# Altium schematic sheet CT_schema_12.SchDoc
size 389 x 385 mm
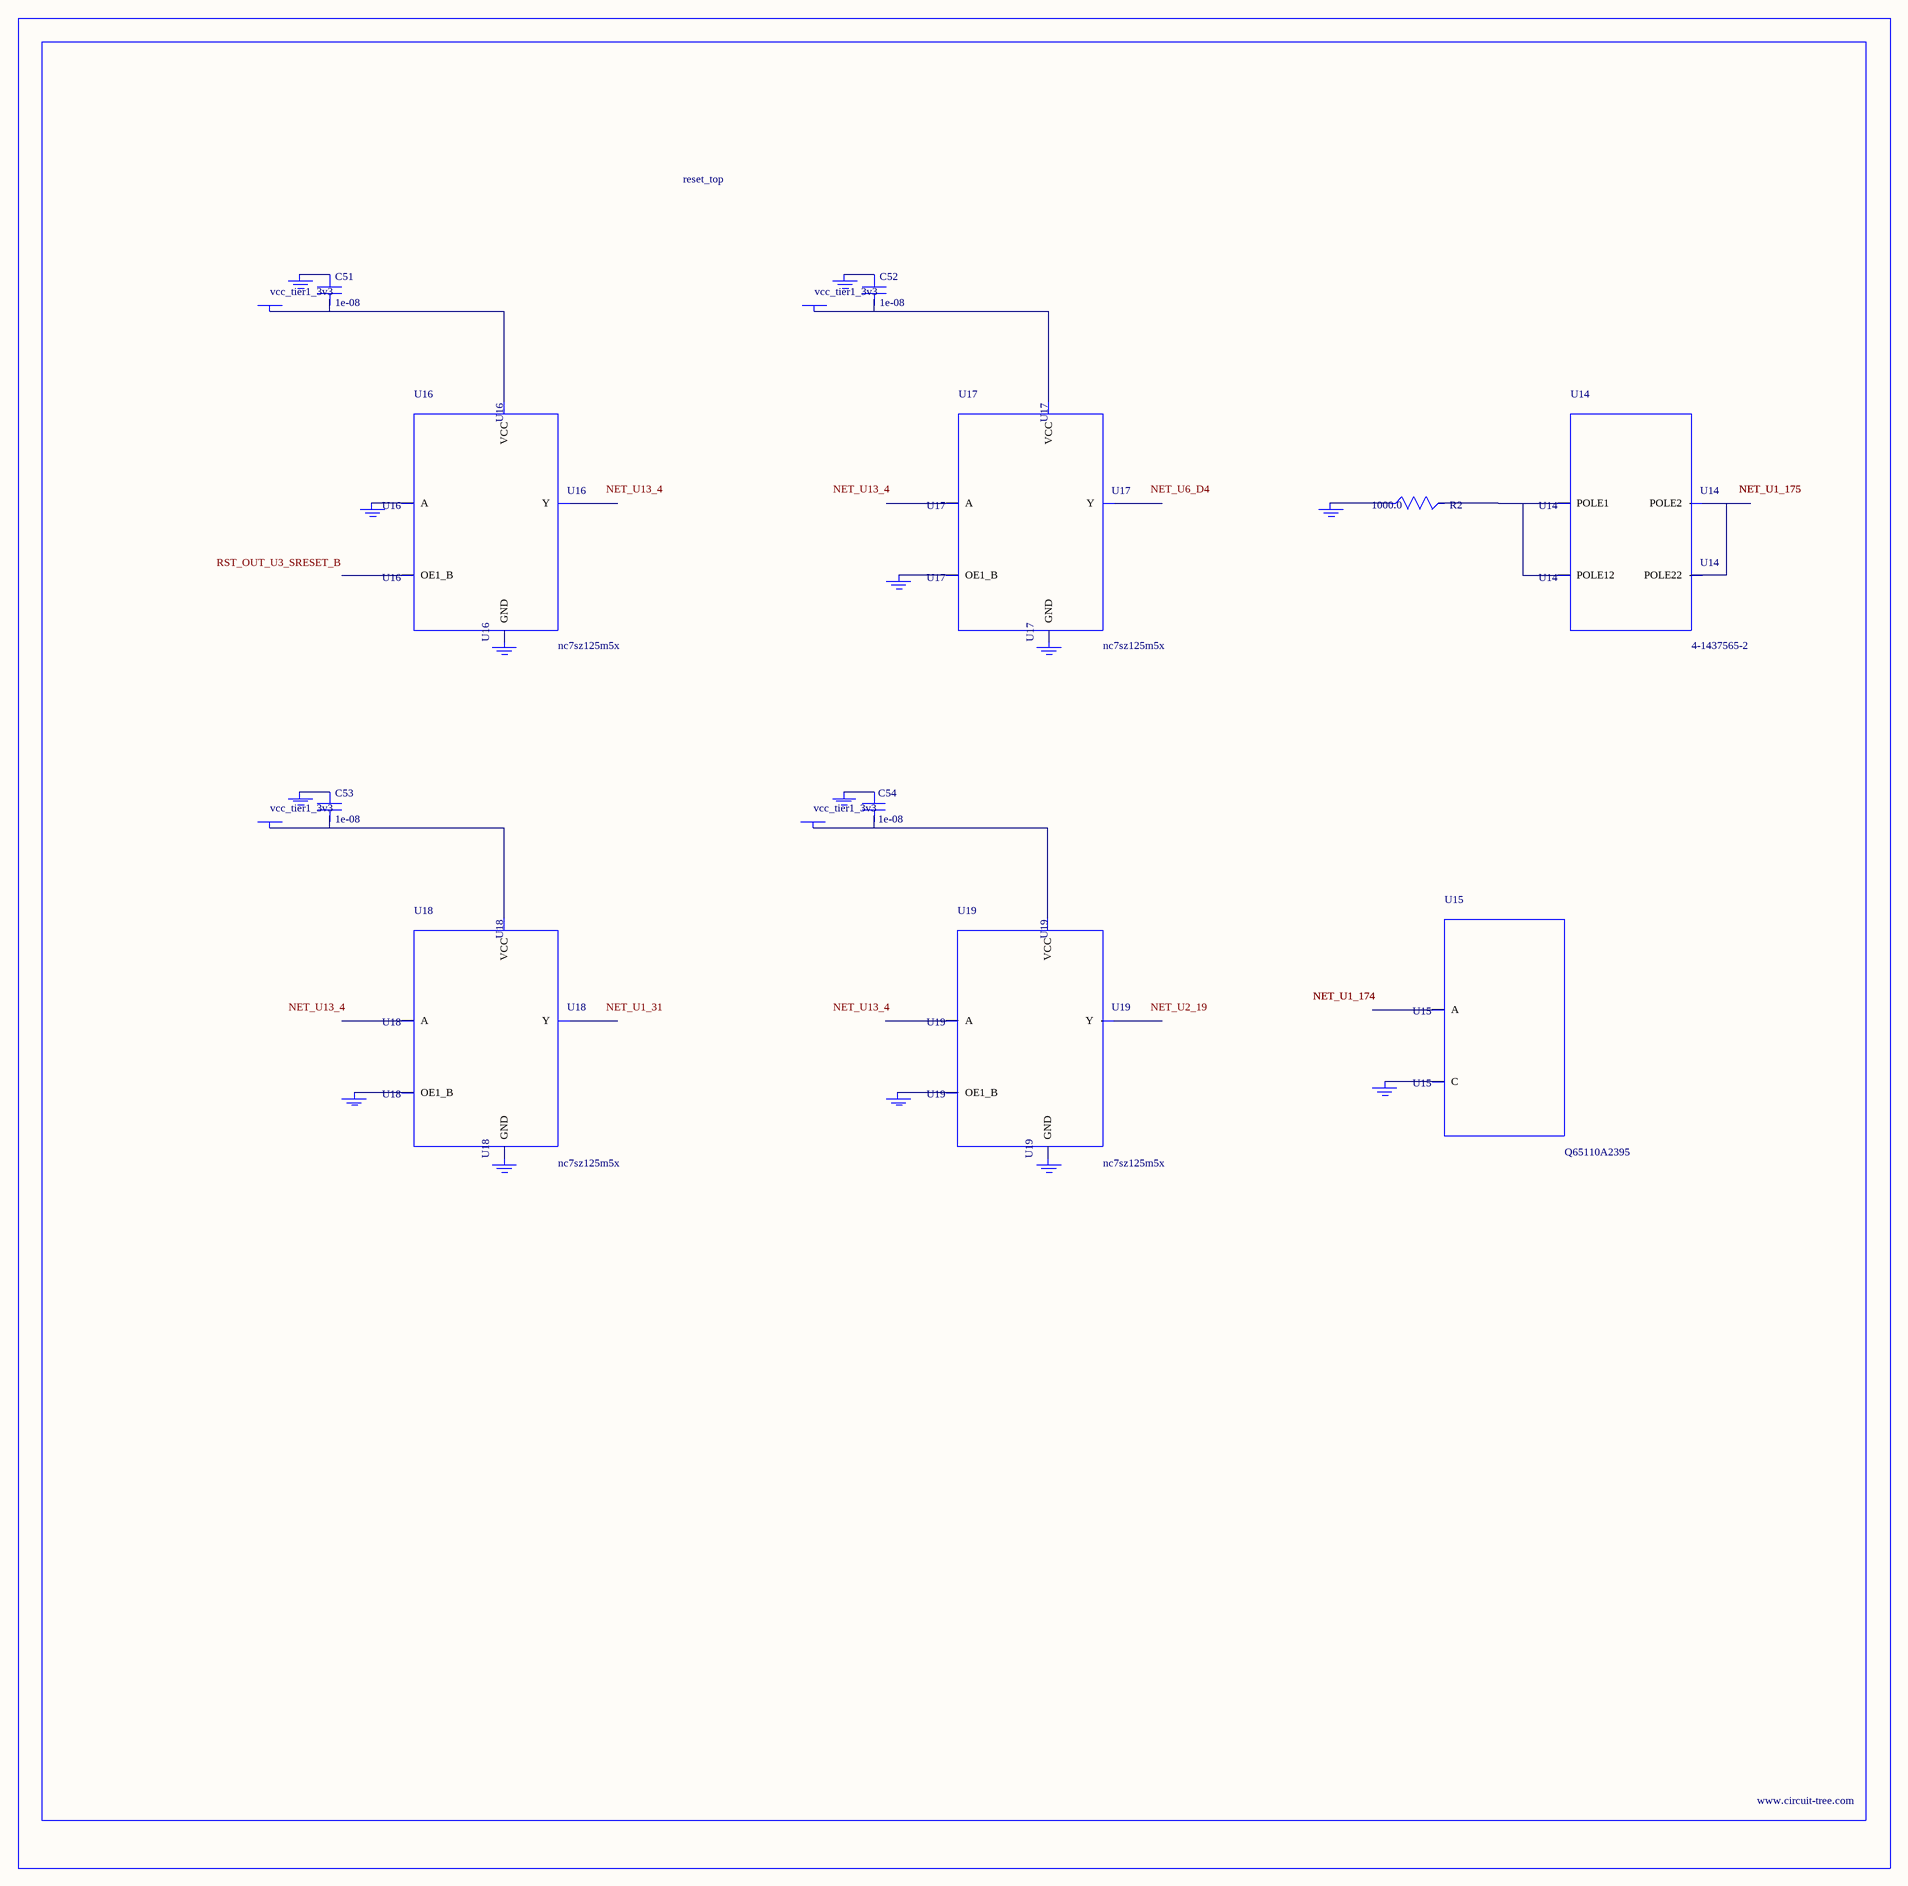
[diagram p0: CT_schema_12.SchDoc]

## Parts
BORDER11  (no value)
C51  1e-08  [C0402]
C52  1e-08  [C0402]
C53  1e-08  [C0402]
C54  1e-08  [C0402]
GND_INSTANCE_11_0  (no value)
GND_INSTANCE_11_1  (no value)
GND_INSTANCE_11_2  (no value)
GND_INSTANCE_11_3  (no value)
GND_INSTANCE_11_4  (no value)
GND_INSTANCE_11_5  (no value)
GND_INSTANCE_11_6  (no value)
GND_INSTANCE_11_7  (no value)
GND_INSTANCE_11_8  (no value)
GND_INSTANCE_11_9  (no value)
GND_INSTANCE_11_10  (no value)
GND_INSTANCE_11_11  (no value)
GND_INSTANCE_11_12  (no value)
GND_INSTANCE_11_13  (no value)
POWER_INSTANCE_11_0  vcc_tier1_3v3
POWER_INSTANCE_11_1  vcc_tier1_3v3
POWER_INSTANCE_11_2  vcc_tier1_3v3
POWER_INSTANCE_11_3  vcc_tier1_3v3
R2  1000.0  [R0603]
U14  4-1437565-2  [SW_4-1437565-2]
U15  Q65110A2395  [LGM67K-G1J2-24-Z]
U16  nc7sz125m5x  [NC7SZ125M5X]
U17  nc7sz125m5x  [NC7SZ125M5X]
U18  nc7sz125m5x  [NC7SZ125M5X]
U19  nc7sz125m5x  [NC7SZ125M5X]

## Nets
NetC51_1: C51.1 GND_INSTANCE_11_2.0(GND)
NetC51_2: C51.2 POWER_INSTANCE_11_0.0(PWR) U16.5(VCC)
NetC52_1: C52.1 GND_INSTANCE_11_5.0(GND)
NetC52_2: C52.2 POWER_INSTANCE_11_1.0(PWR) U17.5(VCC)
NetC53_1: C53.1 GND_INSTANCE_11_8.0(GND)
NetC53_2: C53.2 POWER_INSTANCE_11_2.0(PWR) U18.5(VCC)
NetC54_1: C54.1 GND_INSTANCE_11_11.0(GND)
NetC54_2: C54.2 POWER_INSTANCE_11_3.0(PWR) U19.5(VCC)
NetGND_INSTANCE_11_0_0: GND_INSTANCE_11_0.0(GND) R2.1
NetGND_INSTANCE_11_1_0: GND_INSTANCE_11_1.0(GND) U15.C
NetGND_INSTANCE_11_3_0: GND_INSTANCE_11_3.0(GND) U16.2(A)
NetGND_INSTANCE_11_4_0: GND_INSTANCE_11_4.0(GND) U16.3(GND)
NetGND_INSTANCE_11_6_0: GND_INSTANCE_11_6.0(GND) U17.1(OE1_B)
NetGND_INSTANCE_11_7_0: GND_INSTANCE_11_7.0(GND) U17.3(GND)
NetGND_INSTANCE_11_9_0: GND_INSTANCE_11_9.0(GND) U18.1(OE1_B)
NetGND_INSTANCE_11_10_0: GND_INSTANCE_11_10.0(GND) U18.3(GND)
NetGND_INSTANCE_11_12_0: GND_INSTANCE_11_12.0(GND) U19.1(OE1_B)
NetGND_INSTANCE_11_13_0: GND_INSTANCE_11_13.0(GND) U19.3(GND)
NetR2_2: R2.2 U14.1(POLE1) U14.2(POLE12)
NetU14_3: U14.3(POLE2) U14.4(POLE22)

Not connected (* = marked no-connect by the designer): U15 A; U16 1(OE1_B) 4(Y); U17 2(A) 4(Y); U18 2(A) 4(Y); U19 2(A) 4(Y)

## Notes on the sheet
- Labels drawn without touching a wire or pin: NET_U1_31, NET_U2_19, NET_U6_D4, NET_U13_4, RST_OUT_U3_SRESET_B

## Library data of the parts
BORDER11 = BORDER_PAGE11
C51-C54 = C0402C103K3RAC
GND_INSTANCE_11_0-GND_INSTANCE_11_13 = GND
POWER_INSTANCE_11_0-POWER_INSTANCE_11_3 = PWR
R2 = RC0603JR-071KL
